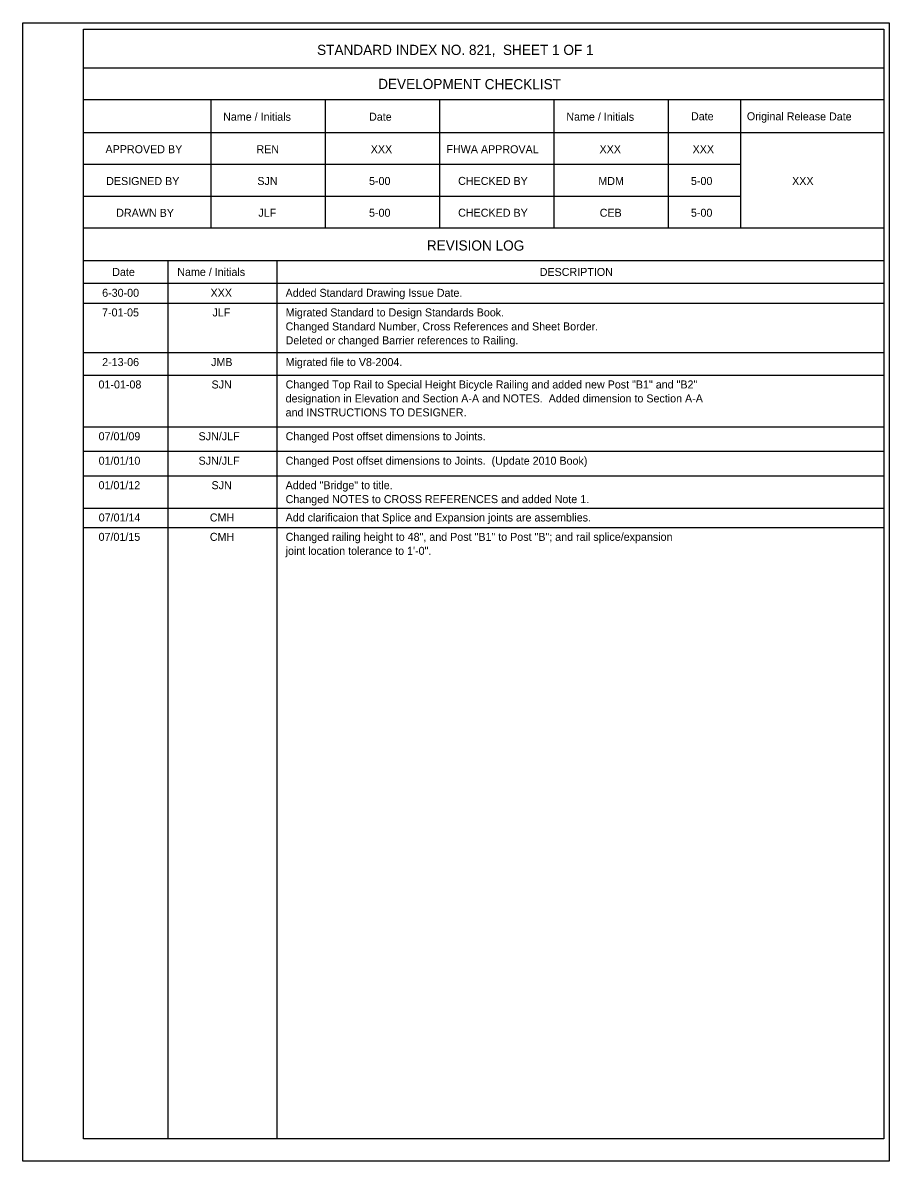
# Model space of a CAD drawing. Extents: x 120680.2 to 120752.3, y 120667.6 to 120707.3.
# Drawn here: x 120730.5 to 120752.31, y 120677.05 to 120705.72 of the extents above; entities that cross this region are included whole.
import ezdxf

# ---------------------------------------------------------------- set-up
doc = ezdxf.new("R2010")
doc.units = 0
for name, color, linetype in [('Border', 7, 'Continuous'), ('Dimension', 7, 'Continuous'), ('PlotBorder_dp', 7, 'Continuous'), ('TextStructures', 7, 'Continuous')]:
    doc.layers.add(name, color=color, linetype=linetype)

msp = doc.modelspace()

# ---------------------------------------------------------------- linework, layer by layer
at = {"layer": 'Border'}
for p, q in [((120752.178, 120704.573), (120732.031, 120704.573)), ((120752.178, 120703.773), (120732.031, 120703.773)), ((120735.231, 120703.773), (120735.231, 120700.545)), ((120738.111, 120703.773), (120738.111, 120700.545)), ((120740.991, 120703.773), (120740.991, 120700.545)), ((120743.871, 120703.773), (120743.871, 120700.545)), ((120746.751, 120703.773), (120746.751, 120700.545)), ((120748.566, 120703.773), (120748.566, 120700.545)), ((120752.178, 120702.945), (120732.031, 120702.945)), ((120748.566, 120702.145), (120732.031, 120702.145)), ((120748.566, 120701.345), (120732.031, 120701.345)), ((120752.178, 120700.545), (120732.031, 120700.545)), ((120752.178, 120699.718), (120732.031, 120699.718)), ((120734.151, 120699.718), (120734.151, 120677.611)), ((120736.894, 120699.718), (120736.894, 120677.611)), ((120752.178, 120699.154), (120732.031, 120699.154))]:
    msp.add_line(p, q, dxfattribs=at)
msp.add_lwpolyline([(120732.031, 120705.554), (120752.178, 120705.554), (120752.178, 120677.611), (120732.031, 120677.611)], close=True, dxfattribs=at)
at = {"layer": 'Dimension'}
for p, q in [((120732.031, 120698.66), (120752.178, 120698.66)), ((120732.031, 120697.41), (120752.178, 120697.41)), ((120732.031, 120696.846), (120752.178, 120696.846)), ((120732.031, 120695.542), (120752.178, 120695.542)), ((120732.031, 120694.926), (120752.178, 120694.926)), ((120732.031, 120694.31), (120752.178, 120694.31)), ((120732.031, 120693.497), (120752.178, 120693.497)), ((120732.031, 120693.009), (120752.178, 120693.009))]:
    msp.add_line(p, q, dxfattribs=at)
at = {"layer": 'PlotBorder_dp'}
msp.add_line((120730.501, 120677.05), (120730.501, 120677.05), dxfattribs=at)
msp.add_lwpolyline([(120730.501, 120705.716), (120752.314, 120705.716), (120752.314, 120677.05), (120730.501, 120677.05)], close=True, dxfattribs=at)

# ---------------------------------------------------------------- texts
at = {"layer": 'TextStructures'}
for s, height, p in [('STANDARD INDEX NO. 821,  SHEET 1 OF 1', 0.256, (120737.91, 120704.906)), ('REN', 0.2016, (120736.383, 120702.432)), ('XXX', 0.2016, (120739.261, 120702.432)), ('XXX', 0.2016, (120745.021, 120702.432)), ('XXX', 0.2016, (120747.364, 120702.432)), ('SJN', 0.2016, (120736.406, 120701.632)), ('5-00', 0.2016, (120739.218, 120701.632)), ('MDM', 0.2016, (120744.991, 120701.632)), ('5-00', 0.2016, (120747.322, 120701.632)), ('XXX', 0.2016, (120749.869, 120701.632)), ('JLF', 0.2016, (120736.431, 120700.832)), ('5-00', 0.2016, (120739.218, 120700.832)), ('CEB', 0.2016, (120745.025, 120700.832)), ('5-00', 0.2016, (120747.322, 120700.832)), ('DESCRIPTION', 0.2016, (120743.515, 120699.341)), ('6-30-00', 0.2016, (120732.499, 120698.816)), ('XXX', 0.2016, (120735.228, 120698.816)), ('Added Standard Drawing Issue Date.', 0.2016, (120737.117, 120698.816)), ('7-01-05', 0.2016, (120732.497, 120698.322)), ('JLF', 0.2016, (120735.278, 120698.322)), ('Migrated Standard to Design Standards Book.', 0.2016, (120737.118, 120698.322)), ('Changed Standard Number, Cross References and Sheet Border.', 0.2016, (120737.118, 120697.97)), ('Deleted or changed Barrier references to Railing.', 0.2016, (120737.118, 120697.619)), ('2-13-06', 0.2016, (120732.499, 120697.072)), ('JMB', 0.2016, (120735.241, 120697.072)), ('Migrated file to V8-2004.', 0.2016, (120737.118, 120697.072)), ('01-01-08', 0.2016, (120732.407, 120696.508)), ('SJN', 0.2016, (120735.253, 120696.508)), ('Changed Top Rail to Special Height Bicycle Railing and added new Post "B1" and "B2" ', 0.2016, (120737.118, 120696.508)), ('designation in Elevation and Section A-A and NOTES.  Added dimension to Section A-A ', 0.2016, (120737.118, 120696.157)), ('and INSTRUCTIONS TO DESIGNER.', 0.2016, (120737.118, 120695.805)), ('07/01/09', 0.2016, (120732.41, 120695.204)), ('SJN/JLF', 0.2016, (120734.926, 120695.204)), ('Changed Post offset dimensions to Joints.', 0.2016, (120737.118, 120695.204)), ('01/01/10', 0.2016, (120732.411, 120694.588)), ('SJN/JLF', 0.2016, (120734.926, 120694.588)), ('Changed Post offset dimensions to Joints.  (Update 2010 Book)', 0.2016, (120737.118, 120694.588)), ('01/01/12', 0.2016, (120732.408, 120693.972)), ('SJN', 0.2016, (120735.253, 120693.972)), ('Added "Bridge" to title.', 0.2016, (120737.118, 120693.972)), ('Changed NOTES to CROSS REFERENCES and added Note 1.', 0.2016, (120737.118, 120693.621)), ('07/01/14', 0.2016, (120732.412, 120693.159)), ('CMH', 0.2016, (120735.21, 120693.159)), ('Add clarificaion that Splice and Expansion joints are assemblies.', 0.2016, (120737.118, 120693.159)), ('07/01/15', 0.2016, (120732.409, 120692.671)), ('CMH', 0.2016, (120735.21, 120692.671)), ('Changed railing height to 48", and Post "B1" to Post "B"; and rail splice/expansion', 0.2016, (120737.118, 120692.671)), ('joint location tolerance to 1\'-0".', 0.2016, (120737.118, 120692.319))]:
    msp.add_text(s, height=height, dxfattribs=at).set_placement(p)
for s, height, p in [('DEVELOPMENT CHECKLIST', 0.256, (120739.447, 120704.05)), ('Name / Initials', 0.2016, (120735.544, 120703.252)), ('Date', 0.2016, (120739.218, 120703.251)), ('Name / Initials', 0.2016, (120744.184, 120703.252)), ('Date', 0.2016, (120747.323, 120703.262)), ('Original Release Date', 0.2016, (120748.73, 120703.262)), ('APPROVED BY', 0.2016, (120732.583, 120702.434)), ('FHWA APPROVAL', 0.2016, (120741.166, 120702.434)), ('DESIGNED BY', 0.2016, (120732.6, 120701.632)), ('CHECKED BY', 0.2016, (120741.461, 120701.634)), ('DRAWN BY', 0.2016, (120732.853, 120700.832)), ('CHECKED BY', 0.2016, (120741.461, 120700.834)), ('REVISION LOG', 0.256, (120740.672, 120699.984)), ('Date', 0.2016, (120732.753, 120699.341)), ('Name / Initials', 0.2016, (120734.39, 120699.343))]:
    msp.add_text(s, height=height, rotation=359.8756, dxfattribs=at).set_placement(p)

doc.saveas('drawing.dxf')
